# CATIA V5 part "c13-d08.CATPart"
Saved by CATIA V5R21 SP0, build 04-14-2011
Part number: Part1
Material "Alpine Fir": density 500 kg/m3, Young's modulus 1.7e+10 Pa, Poisson ratio 0.45, thermal expansion 3.75e-06 1/K
Bounding box of the stored display mesh (mm): x -163 to 95, y -77.362 to 77.362, z -85 to 85
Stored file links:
  D:\CATIA V5R21 E-RESOURCES\CATIA-V5R21\catia-v5r21-Prts\c13_catia_v5r21_prt\c13_catia_v5r21_figr_13-32 & 33\c13-d08.CATPart
  C:\Program Files\Dassault Systemes\B21\win_b64\startup\materials\Catalog.CATMaterial
  C:\Program Files\Dassault Systemes\B21\win_b64\startup\materials\alpin_fir.jpg
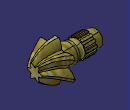
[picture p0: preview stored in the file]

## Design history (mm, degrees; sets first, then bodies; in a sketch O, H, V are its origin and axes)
Set1
  Plane1: type Offset, RefPlane face of Shaft1, Offset 45, reversed
  Plane2: type Offset, RefPlane Plane1, Offset 50, reversed
Body1 (main body), material "Alpine Fir"
  Sketch1 on zx-plane, origin (0, 0, 0), H (-1, 0, 0), V (0, 0, 1)
    axis line L1 (0, 0) -> (170, 0)
    line L2 (0, 0) -> (0, -45)
    point P2 (0, -45)
    line L3 (0, -45) -> (5, -45)
    point P3 (5, -45)
    line L4 (5, -45) -> (5, -39)
    line L5 (5, -39) -> (51, -39)
    line L6 (51, -39) -> (51, -38)
    point P6 (51, -38)
    line L7 (51, -38) -> (61, -38)
    point P7 (61, -38)
    line L8 (61, -38) -> (61, -36)
    point P8 (61, -36)
    arc A1 centre (72, -36) radius 11 from (61, -36) to (83, -36) cw
    point P10 (83, -36)
    line L9 (83, -36) -> (131, -36)
    line L10 (131, -36) -> (131, -32.5)
    line L11 (131, -32.5) -> (163, -32.5)
    line L12 (163, -32.5) -> (163, 0)
    point P14 (163, 0)
    line L13 (163, 0) -> (0, 0)
    "Radius" L11 L1 = 32.5
    "Radius" L9 L1 = 36
    "Radius" P7 L1 = 38
    "Radius" L5 L1 = 39
    "Radius" P3 L1 = 45
    length L11 = 32
    length L9 = 48
    distance P10 P8 = 22
    distance P7 P6 = 10
    length L5 = 46
    distance P3 P2 = 5
    horizontal: L1 H, L3 H, L5 H, L7 H, L9 H, L11 H, L13 H
    vertical: L2 V, L4 V, L6 V, L8 V, L12 V, L10 V
    tangency: A1 L8
    coincidence: P14 L1
  Shaft1: profile Sketch1, axis Sketch1.L1, angle 360
  Sketch2 on face of Shaft1, origin (-131, 0, 0), H (0, -1, 0), V (0, 0, 1)
    projected circle E1 centre (0, 0) radius 36 from edge [face of Shaft1 | face of Shaft1]
    projected arc E2 centre (0, 0) radius 36 from (5, 35.6511) to (-5, 35.6511) ccw from edge [face of Shaft1 | face of Shaft1]
    axis line L1 (0, 0) -> (0, 17.1744)
    point P2 (-5, 35.6511)
    line L2 (-5, 35.6511) -> (-5, 40.6511)
    point P3 (-5, 40.6511)
    line L3 (-5, 40.6511) -> (0, 40.6511)
    point P4 (0, 40.6511)
    point P5 (0, 40.6511)
    point P6 (5, 40.6511)
    line L4 (5, 40.6511) -> (0, 40.6511)
    point P7 (5, 35.6511)
    line L5 (5, 35.6511) -> (5, 40.6511)
    length L5 = 5
    distance L5 L2 = 10
    vertical: L1 V, L2 V
    coincidence: P2 E1, P4 L1, P4 P5
    horizontal: L3 H
    symmetry: P4 P5 L1, P3 P6 L1, L3 L4 L1, P2 P7 L1, L2 L5 L1
  Pad1: profile Sketch2, direction (1, 0, 0), length 48
  CircPattern1: of Pad1, instances 13, angular step 27.6923 {= 360.0*1 deg/CircPattern1.AngularNumber}, axis from face of Shaft1
  Loft1: solid, Sections (Sketch5; Sketch4; Sketch3)
  Sketch3 on Plane2, origin (95, 0, 0), H (0, -1, 0), V (0, 0, 1)
    construction line L1 through (0, 0) direction (1, 0)
    construction line L2 through (0, 0) direction (0, 1)
    arc A1 centre (23.3627, 6.7195) radius 24.375 from (13.5018, 29.0108) to (2.0971, 18.6324) ccw
    line L3 (18.3732, 26.1983) -> (13.5018, 29.0108)
    arc A2 centre (-5.8621, 23.5924) radius 24.375 from (15.0875, 11.1324) to (18.3732, 26.1983) ccw
    arc A3 centre (0, 0) radius 18.75 from (17.1847, 7.5) to (15.0875, 11.1324) ccw
    arc A4 centre (17.5006, -16.873) radius 24.375 from (31.875, 2.8125) to (17.1847, 7.5) ccw
    line L4 (31.875, -2.8125) -> (31.875, 2.8125)
    arc A5 centre (17.5006, 16.873) radius 24.375 from (17.1847, -7.5) to (31.875, -2.8125) ccw
    arc A6 centre (0, 0) radius 18.75 from (15.0875, -11.1324) to (17.1847, -7.5) ccw
    arc A7 centre (-5.8621, -23.5924) radius 24.375 from (18.3732, -26.1983) to (15.0875, -11.1324) ccw
    line L5 (13.5018, -29.0108) -> (18.3732, -26.1983)
    arc A8 centre (23.3627, -6.7195) radius 24.375 from (2.0971, -18.6324) to (13.5018, -29.0108) ccw
    arc A9 centre (0, 0) radius 18.75 from (-2.0971, -18.6324) to (2.0971, -18.6324) ccw
    arc A10 centre (-23.3627, -6.7195) radius 24.375 from (-13.5018, -29.0108) to (-2.0971, -18.6324) ccw
    line L6 (-18.3732, -26.1983) -> (-13.5018, -29.0108)
    arc A11 centre (5.8621, -23.5924) radius 24.375 from (-15.0875, -11.1324) to (-18.3732, -26.1983) ccw
    arc A12 centre (0, 0) radius 18.75 from (-17.1847, -7.5) to (-15.0875, -11.1324) ccw
    arc A13 centre (-17.5006, 16.873) radius 24.375 from (-31.875, -2.8125) to (-17.1847, -7.5) ccw
    line L7 (-31.875, 2.8125) -> (-31.875, -2.8125)
    arc A14 centre (-17.5006, -16.873) radius 24.375 from (-17.1847, 7.5) to (-31.875, 2.8125) ccw
    arc A15 centre (0, 0) radius 18.75 from (-15.0875, 11.1324) to (-17.1847, 7.5) ccw
    arc A16 centre (5.8621, 23.5924) radius 24.375 from (-18.3732, 26.1983) to (-15.0875, 11.1324) ccw
    line L8 (-13.5018, 29.0108) -> (-18.3732, 26.1983)
    arc A17 centre (-23.3627, 6.7195) radius 24.375 from (-2.0971, 18.6324) to (-13.5018, 29.0108) ccw
    arc A18 centre (0, 0) radius 18.75 from (2.0971, 18.6324) to (-2.0971, 18.6324) ccw
  Sketch4 on Plane1, origin (45, 0, 0), H (0, -1, 0), V (0, 0, 1)
    construction line L1 through (0, 0) direction (0.9659, -0.2588)
    construction line L2 through (0, 0) direction (0.2588, 0.9659)
    arc A1 centre (0, 0) radius 37.5 from (5.5935, -37.0805) to (13.6962, -34.9094) ccw
    arc A2 centre (-41.655, -25.0745) radius 48.75 from (-11.0664, -63.0336) to (5.5935, -37.0805) ccw
    arc A3 centre (48.6115, -0.8876) radius 48.75 from (13.6962, -34.9094) to (41.1006, -49.0555) ccw
    line L3 (49.0555, -41.1006) -> (41.1006, -49.0555)
    arc A4 centre (0.8876, -48.6115) radius 48.75 from (49.0555, -41.1006) to (34.9094, -13.6962) ccw
    arc A5 centre (0, 0) radius 37.5 from (34.9094, -13.6962) to (37.0805, -5.5935) ccw
    arc A6 centre (25.0745, 41.655) radius 48.75 from (37.0805, -5.5935) to (63.0336, 11.0664) ccw
    line L4 (60.1219, 21.933) -> (63.0336, 11.0664)
    arc A7 centre (42.5426, -23.5371) radius 48.75 from (60.1219, 21.933) to (29.3159, 23.3843) ccw
    arc A8 centre (0, 0) radius 37.5 from (29.3159, 23.3843) to (23.3843, 29.3159) ccw
    arc A9 centre (-23.5371, 42.5426) radius 48.75 from (23.3843, 29.3159) to (21.933, 60.1219) ccw
    line L5 (11.0664, 63.0336) -> (21.933, 60.1219)
    arc A10 centre (41.655, 25.0745) radius 48.75 from (11.0664, 63.0336) to (-5.5935, 37.0805) ccw
    arc A11 centre (0, 0) radius 37.5 from (-5.5935, 37.0805) to (-13.6962, 34.9094) ccw
    arc A12 centre (-48.6115, 0.8876) radius 48.75 from (-13.6962, 34.9094) to (-41.1006, 49.0555) ccw
    line L6 (-49.0555, 41.1006) -> (-41.1006, 49.0555)
    arc A13 centre (-0.8876, 48.6115) radius 48.75 from (-49.0555, 41.1006) to (-34.9094, 13.6962) ccw
    arc A14 centre (0, 0) radius 37.5 from (-34.9094, 13.6962) to (-37.0805, 5.5935) ccw
    arc A15 centre (-25.0745, -41.655) radius 48.75 from (-37.0805, 5.5935) to (-63.0336, -11.0664) ccw
    line L7 (-60.1219, -21.933) -> (-63.0336, -11.0664)
    arc A16 centre (-42.5426, 23.5371) radius 48.75 from (-60.1219, -21.933) to (-29.3159, -23.3843) ccw
    arc A17 centre (0, 0) radius 37.5 from (-29.3159, -23.3843) to (-23.3843, -29.3159) ccw
    arc A18 centre (23.5371, -42.5426) radius 48.75 from (-23.3843, -29.3159) to (-21.933, -60.1219) ccw
    line L8 (-11.0664, -63.0336) -> (-21.933, -60.1219)
  Sketch5 on face of Shaft1, origin (0, 0, 0), H (0, 1, 0), V (0, 0, 1)
    arc A1 centre (44.9945, 46.6682) radius 65 from (-20, 45.8258) to (-7.5, 85) cw
    point P1 (-7.5, 85)
    point P2 (7.5, 85)
    arc A2 centre (-44.9945, 46.6682) radius 65 from (20, 45.8258) to (7.5, 85) ccw
    line L1 (-7.5, 85) -> (7.5, 85)
    point P3 (7.5, 85)
    point P4 (20, 45.8258)
    point P5 (-20, 45.8258)
    point P6 (0, 0)
    arc A3 centre (0, 0) radius 50 from (29.6863, 40.2334) to (20, 45.8258) ccw
    arc A4 centre (-17.9186, 62.3005) radius 65 from (-49.6863, 5.5924) to (-77.3622, 36.0048) cw
    arc A5 centre (-62.9132, -15.6323) radius 65 from (-29.6863, 40.2334) to (-69.8622, 48.9952) ccw
    line L2 (-77.3622, 36.0048) -> (-69.8622, 48.9952)
    arc A6 centre (-62.9132, 15.6323) radius 65 from (-29.6863, -40.2334) to (-69.8622, -48.9952) cw
    arc A7 centre (-17.9186, -62.3005) radius 65 from (-49.6863, -5.5924) to (-77.3622, -36.0048) ccw
    line L3 (-69.8622, -48.9952) -> (-77.3622, -36.0048)
    arc A8 centre (-44.9945, -46.6682) radius 65 from (20, -45.8258) to (7.5, -85) cw
    arc A9 centre (44.9945, -46.6682) radius 65 from (-20, -45.8258) to (-7.5, -85) ccw
    line L4 (7.5, -85) -> (-7.5, -85)
    arc A10 centre (17.9186, -62.3005) radius 65 from (49.6863, -5.5924) to (77.3622, -36.0048) cw
    arc A11 centre (62.9132, 15.6323) radius 65 from (29.6863, -40.2334) to (69.8622, -48.9952) ccw
    line L5 (77.3622, -36.0048) -> (69.8622, -48.9952)
    arc A12 centre (62.9132, -15.6323) radius 65 from (29.6863, 40.2334) to (69.8622, 48.9952) cw
    arc A13 centre (17.9186, 62.3005) radius 65 from (49.6863, 5.5924) to (77.3622, 36.0048) ccw
    line L6 (69.8622, 48.9952) -> (77.3622, 36.0048)
    arc A14 centre (0, 0) radius 50 from (-49.6863, 5.5924) to (-49.6863, -5.5924) ccw
    arc A15 centre (0, 0) radius 50 from (-29.6863, -40.2334) to (-20, -45.8258) ccw
    arc A16 centre (0, 0) radius 50 from (20, -45.8258) to (29.6863, -40.2334) ccw
    arc A17 centre (0, 0) radius 50 from (49.6863, -5.5924) to (49.6863, 5.5924) ccw
    arc A18 centre (0, 0) radius 50 from (-20, 45.8258) to (-29.6863, 40.2334) ccw
    distance P4 P5 = 40
    radius A2 = 65
    length L1 = 15
    distance P6 L1 = 85
    radius A3 = 50
    symmetry: P1 P2 V, A1 A2 V, P4 P5 V
    coincidence: P3 A2, P6 O, P5 A3, A3 A14, A14 A15, A15 A16, A16 A17, A3 A18
    horizontal: L1 H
